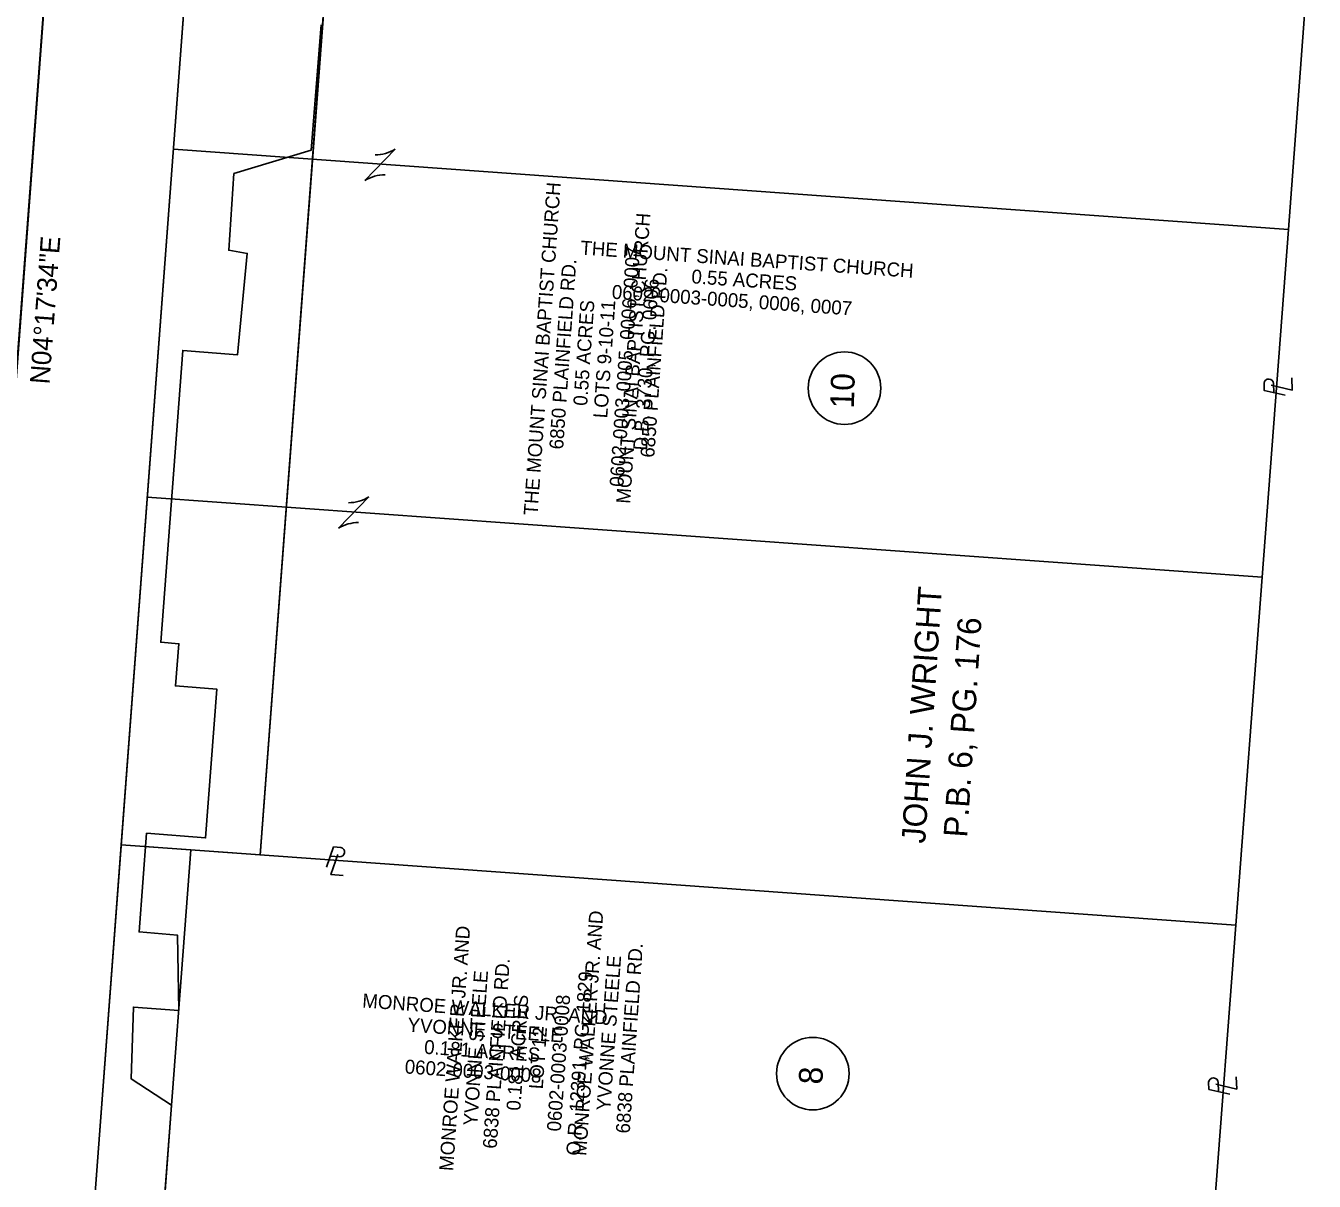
# Model space of a CAD drawing. Extents: x 204354 to 231038, y 361459 to 365260.
# Drawn here: x 220550.5 to 220735.2, y 361736.1 to 361901.8 of the extents above; entities that cross this region are included whole.
import ezdxf

# ---------------------------------------------------------------- set-up
doc = ezdxf.new("R2010")
doc.units = 0
for name, color, linetype in [('CM_Corridor_Point_Control', 7, 'Continuous'), ('CM_Corridor_Range_Conceptual', 7, 'Continuous'), ('DT_P_Contour_Minor', 7, 'Continuous'), ('DT_P_Contour_Text', 7, 'Continuous'), ('DT_P_Triangles', 7, 'Continuous'), ('DT_X_Contour_Minor', 7, 'Continuous'), ('MD_P_ACSC_B', 7, 'Continuous'), ('MD_P_Intersection_MatchLine', 7, 'Continuous'), ('MD_P_SW_BOT', 7, 'Continuous'), ('MD_P_SW_TOP', 7, 'Continuous'), ('PV_P_Walk', 7, 'Continuous'), ('SC_Shading1', 7, 'Continuous')]:
    doc.layers.add(name, color=color, linetype=linetype)

msp = doc.modelspace()

# ---------------------------------------------------------------- linework, layer by layer
at = {"layer": 'CM_Corridor_Range_Conceptual'}
msp.add_line((220527.43, 361562.35), (220572.38, 362161.22), dxfattribs=at)
msp.add_line((220527.43, 361562.35), (220572.38, 362161.22), dxfattribs=at)
at = {"layer": 'DT_P_Contour_Text'}
for centre in [(220667.83, 361849.84), (220663.29, 361751.57)]:
    msp.add_circle(centre, 5.2, dxfattribs=at)
at = {"layer": 'DT_P_Triangles'}
msp.add_lwpolyline([(220569.34, 361719.9), (220571.38, 361747.03), (220565.61, 361750.81), (220565.92, 361761.1), (220572.4, 361760.62), (220572.21, 361771.42), (220566.72, 361771.88), (220567.79, 361786.04), (220576.26, 361785.35), (220577.86, 361806.69), (220571.92, 361807.16), (220572.44, 361813.2), (220569.84, 361813.42), (220572.98, 361855.24), (220580.84, 361854.63), (220582.23, 361869.16), (220579.58, 361869.62), (220580.32, 361880.61), (220591.41, 361883.96), (220592.81, 361901.94)], dxfattribs=at)
at = {"layer": 'MD_P_Intersection_MatchLine'}
for p, q in [((220584.1, 361782.9), (220595.33, 361932.5)), ((220584.1, 361782.92), (220595.33, 361932.5)), ((220564.15, 361784.36), (220584.1, 361782.92)), ((220574.13, 361783.64), (220570.38, 361733.77))]:
    msp.add_line(p, q, dxfattribs=at)
at = {"layer": 'MD_P_SW_BOT'}
for p, q in [((220735.16, 361922.45), (220731.49, 361872.59)), ((220731.49, 361872.59), (220571.64, 361884.08)), ((220599.1, 361879.61), (220603.43, 361884.11)), ((220601.26, 361881.86), (220601.26, 361881.86)), ((220731.49, 361872.59), (220727.71, 361822.73)), ((220729.39, 361849.19), (220729.34, 361850.49)), ((220729.98, 361850.02), (220729.98, 361850.02)), ((220595.31, 361829.75), (220599.64, 361834.25)), ((220727.71, 361822.73), (220567.89, 361834.22)), ((220597.47, 361832), (220597.47, 361832)), ((220727.71, 361822.73), (220723.92, 361772.87)), ((220723.92, 361772.87), (220564.15, 361784.36)), ((220594.14, 361782.73), (220595.44, 361782.64)), ((220594.9, 361782.06), (220594.9, 361782.06)), ((220720.14, 361723.02), (220723.92, 361772.87)), ((220721.45, 361748.99), (220721.4, 361750.29)), ((220722.04, 361749.82), (220722.04, 361749.82))]:
    msp.add_line(p, q, dxfattribs=at)
for points in [[(220729.01, 361850.25), (220732, 361849.56), (220731.93, 361851.31)], [(220730.99, 361848.83), (220728, 361849.5), (220727.97, 361850.54)], [(220593.61, 361781.18), (220594.6, 361784.08), (220595.63, 361784)], [(220595.23, 361782.99), (220594.23, 361780.1), (220595.97, 361779.98)], [(220723.05, 361748.63), (220720.06, 361749.3), (220720.03, 361750.34)], [(220721.07, 361750.05), (220724.06, 361749.36), (220723.99, 361751.11)]]:
    msp.add_lwpolyline(points, dxfattribs=at)
for centre, radius, start, end in [((220600.58, 361888.62), 5.34, 269.5839, 302.2264), ((220601.94, 361875.09), 5.34, 89.5839, 122.2264), ((220728.65, 361850.46), 0.69, 2.5465, 173.4036), ((220596.79, 361838.76), 5.34, 269.5839, 302.2264), ((220598.15, 361825.23), 5.34, 89.5839, 122.2264), ((220595.48, 361783.33), 0.69, 266.3604, 77.2175), ((220720.71, 361750.26), 0.69, 2.5465, 173.4036)]:
    msp.add_arc(centre, radius, start, end, dxfattribs=at)
at = {"layer": 'MD_P_SW_TOP'}
msp.add_line((220519.7, 361460.36), (220580.15, 362265.73), dxfattribs=at)
at = {"layer": 'PV_P_Walk'}
msp.add_line((220549.24, 361585.75), (220590.37, 362133.66), dxfattribs=at)
msp.add_line((220549.24, 361585.75), (220590.37, 362133.66), dxfattribs=at)
at = {"layer": 'SC_Shading1'}
for points in [[(220564.15, 361784.36), (220575.38, 361933.94), (220595.33, 361932.5), (220584.1, 361782.92)], [(220560.41, 361734.5), (220564.15, 361784.36), (220574.13, 361783.64), (220570.38, 361733.78)]]:
    msp.add_lwpolyline(points, close=True, dxfattribs=at)

# ---------------------------------------------------------------- texts
at = {"layer": 'CM_Corridor_Point_Control'}
for s, p in [('MOUNT SINAI BAPTIST CHURCH', (220637.1, 361833.23)), ('6850 PLAINFIELD RD.', (220640.56, 361839.83)), ('MONROE WALKER JR. AND', (220630.81, 361739.74)), ('6838 PLAINFIELD RD.', (220637.04, 361742.94)), ('YVONNE STEELE', (220634.27, 361746.22))]:
    msp.add_text(s, height=2, rotation=86, dxfattribs=at).set_placement(p)
at = {"layer": 'DT_P_Contour_Minor'}
for s, height, rotation, p in [('THE MOUNT SINAI BAPTIST CHURCH', 2, 86, (220623.83, 361831.56)), (' 0602-0003-0005, 0006, 0007', 2, 86, (220636.09, 361834.9)), ('6850 PLAINFIELD RD.', 2, 86, (220627.5, 361841.01)), ('D.B. 3730, PG. 0606', 2, 86, (220639.52, 361840.85)), (' 0.55 ACRES', 2, 86, (220630.89, 361846.52)), ('LOTS 9-10-11', 2, 86, (220633.82, 361845.48)), ('JOHN J. WRIGHT', 3.4, 86.2229, (220679.39, 361784.49)), (' P.B. 6, PG. 176', 3.4, 86.2229, (220685.33, 361784.1)), ('MONROE WALKER JR. AND', 2, 86, (220611.73, 361737.56)), ('6838 PLAINFIELD RD.', 2, 86, (220617.97, 361740.76)), ('YVONNE STEELE', 2, 86, (220615.19, 361744.04)), ('O.R. 12391, PG. 1829', 2, 86, (220629.93, 361739.76)), (' 0.181 ACRES', 2, 86, (220621.31, 361745.47)), (' 0602-0003-0008', 2, 86, (220627.11, 361742.49)), ('LOT 12', 2, 86, (220624.58, 361749.29))]:
    msp.add_text(s, height=height, rotation=rotation, dxfattribs=at).set_placement(p)
at = {"layer": 'DT_P_Contour_Text'}
for s, p in [('10', (220669.17, 361846.89)), ('8', (220664.67, 361749.99))]:
    msp.add_text(s, height=3.4, rotation=88.3143, dxfattribs=at).set_placement(p)
at = {"layer": 'DT_X_Contour_Minor'}
for s, p in [('THE MOUNT SINAI BAPTIST CHURCH', (220629.93, 361869)), (' 0.55 ACRES', (220645.1, 361864.93)), (' 0602-0003-0005, 0006, 0007', (220633.69, 361862.72)), ('MONROE WALKER JR. AND', (220598.67, 361761.06)), ('YVONNE STEELE', (220605.14, 361757.6)), (' 0.181 ACRES', (220606.79, 361754.47)), (' 0602-0003-0008', (220604.01, 361751.66))]:
    msp.add_text(s, height=2, rotation=356, dxfattribs=at).set_placement(p)
at = {"layer": 'MD_P_ACSC_B'}
msp.add_text('N04°17\'34"E', height=2.8, rotation=85.7073, dxfattribs=at).set_placement((220553.86, 361850.34))

doc.saveas('drawing.dxf')
